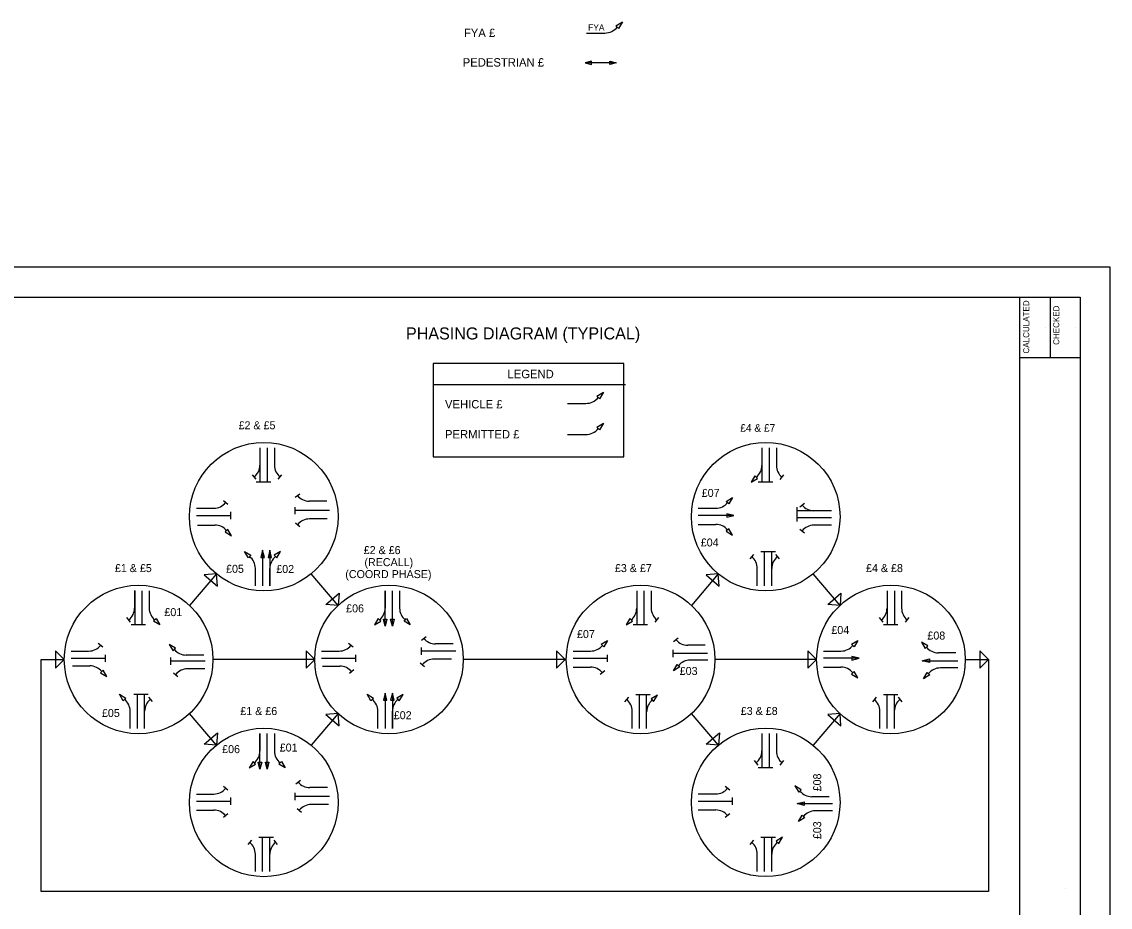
# Model space of a CAD drawing. Extents: x 22.8 to 118.4, y -49.9 to 44.8.
# Drawn here: x 57.13 to 75.22, y 29.96 to 44.69 of the extents above; entities that cross this region are included whole.
import ezdxf

# ---------------------------------------------------------------- set-up
doc = ezdxf.new("R2010")
doc.units = 0
for name, color, linetype in [('SH_Border', 7, 'Continuous'), ('SH_Cut_Line', 7, 'Continuous'), ('SH_Data', 7, 'Continuous'), ('SH_Text', 7, 'Continuous')]:
    doc.layers.add(name, color=color, linetype=linetype)

msp = doc.modelspace()

# ---------------------------------------------------------------- linework, layer by layer
at = {"layer": 'SH_Border'}
for p, q in [((73.72, 19.104), (73.72, 40.104)), ((74.22, 40.104), (74.22, 39.104)), ((73.72, 39.104), (74.72, 39.104))]:
    msp.add_line(p, q, dxfattribs=at)
msp.add_lwpolyline([(43.22, 40.104), (74.72, 40.104), (74.72, 19.104), (43.22, 19.104)], close=True, dxfattribs=at)
at = {"layer": 'SH_Cut_Line'}
msp.add_lwpolyline([(41.22, 18.604), (75.22, 18.604), (75.22, 40.604), (41.22, 40.604)], close=True, dxfattribs=at)
at = {"layer": 'SH_Data'}
for p, q in [((66.513, 44.498), (66.819, 44.498)), ((67.007, 44.001), (66.494, 44.001)), ((74.14, 39.607), (74.14, 39.607)), ((74.64, 39.607), (74.64, 39.607)), ((63.962, 38.652), (67.164, 38.652)), ((66.199, 38.338), (66.504, 38.338)), ((66.199, 37.822), (66.504, 37.822)), ((61.086, 37.6), (61.086, 37.029)), ((61.086, 37.6), (61.086, 37.31)), ((61.207, 37.6), (61.207, 37.029)), ((61.327, 37.6), (61.327, 37.31)), ((69.43, 37.599), (69.43, 37.028)), ((69.43, 37.599), (69.43, 37.308)), ((69.55, 37.599), (69.55, 37.028)), ((69.671, 37.599), (69.671, 37.308)), ((61.022, 37.076), (60.962, 37.151)), ((61.391, 37.076), (61.452, 37.151)), ((69.735, 37.074), (69.795, 37.15)), ((61.146, 37.029), (61.026, 37.029)), ((61.267, 37.029), (61.146, 37.029)), ((69.49, 37.028), (69.37, 37.028)), ((69.611, 37.028), (69.49, 37.028)), ((61.671, 36.777), (61.747, 36.837)), ((60.03, 36.595), (60.32, 36.595)), ((60.554, 36.659), (60.478, 36.72)), ((61.671, 36.495), (61.671, 36.615)), ((62.241, 36.555), (61.671, 36.555)), ((62.196, 36.713), (61.905, 36.713)), ((68.373, 36.594), (68.664, 36.594)), ((70.014, 36.494), (70.014, 36.614)), ((70.585, 36.554), (70.014, 36.554)), ((70.061, 36.617), (70.136, 36.678)), ((70.585, 36.554), (70.295, 36.554)), ((60.03, 36.475), (60.6, 36.475)), ((60.6, 36.414), (60.6, 36.535)), ((62.201, 36.417), (61.91, 36.417)), ((68.965, 36.473), (68.373, 36.473)), ((70.014, 36.373), (70.014, 36.494)), ((70.585, 36.433), (70.014, 36.433)), ((60.046, 36.316), (60.336, 36.316)), ((61.676, 36.353), (61.752, 36.292)), ((68.373, 36.327), (68.664, 36.327)), ((70.061, 36.249), (70.136, 36.188)), ((70.585, 36.313), (70.295, 36.313)), ((61.13, 35.896), (61.13, 35.304)), ((61.251, 35.896), (61.251, 35.304)), ((69.29, 35.828), (69.229, 35.752)), ((69.414, 35.874), (69.534, 35.874)), ((69.474, 35.303), (69.474, 35.874)), ((69.534, 35.874), (69.655, 35.874)), ((69.595, 35.303), (69.595, 35.874)), ((69.658, 35.828), (69.719, 35.752)), ((60.363, 35.503), (59.915, 34.979)), ((61.01, 35.304), (61.01, 35.595)), ((61.251, 35.304), (61.251, 35.595)), ((62.385, 34.979), (61.938, 35.504)), ((68.706, 35.502), (68.259, 34.979)), ((69.354, 35.303), (69.354, 35.593)), ((69.595, 35.303), (69.595, 35.593)), ((70.729, 34.979), (70.282, 35.503)), ((59.001, 35.225), (59.001, 34.934)), ((59.005, 35.224), (59.005, 34.654)), ((59.125, 35.224), (59.125, 34.654)), ((59.246, 35.224), (59.246, 34.934)), ((63.167, 34.633), (63.167, 35.224)), ((63.167, 35.224), (63.167, 34.934)), ((63.288, 34.633), (63.288, 35.224)), ((63.408, 35.224), (63.408, 34.934)), ((67.35, 35.224), (67.35, 34.654)), ((67.35, 35.224), (67.35, 34.934)), ((67.47, 35.224), (67.47, 34.654)), ((67.591, 35.224), (67.591, 34.934)), ((71.511, 35.224), (71.511, 34.654)), ((71.511, 35.224), (71.511, 34.934)), ((71.632, 35.224), (71.632, 34.654)), ((71.752, 35.224), (71.752, 34.934)), ((58.937, 34.7), (58.876, 34.776)), ((67.654, 34.7), (67.715, 34.776)), ((71.447, 34.7), (71.386, 34.776)), ((71.816, 34.7), (71.877, 34.776)), ((59.065, 34.654), (58.945, 34.654)), ((59.186, 34.654), (59.065, 34.654)), ((67.41, 34.654), (67.289, 34.654)), ((67.53, 34.654), (67.41, 34.654)), ((71.571, 34.654), (71.451, 34.654)), ((71.692, 34.654), (71.571, 34.654)), ((63.772, 34.401), (63.847, 34.462)), ((67.963, 34.378), (68.039, 34.439)), ((57.948, 34.22), (58.239, 34.22)), ((58.473, 34.283), (58.397, 34.344)), ((62.111, 34.22), (62.401, 34.22)), ((62.635, 34.283), (62.559, 34.344)), ((63.773, 34.159), (63.773, 34.28)), ((64.344, 34.22), (63.773, 34.22)), ((64.296, 34.338), (64.006, 34.338)), ((66.293, 34.219), (66.583, 34.219)), ((67.955, 34.119), (67.955, 34.24)), ((68.488, 34.315), (68.198, 34.315)), ((70.454, 34.219), (70.745, 34.219)), ((57.948, 34.099), (58.519, 34.099)), ((58.519, 34.039), (58.519, 34.159)), ((59.607, 33.991), (59.607, 34.112)), ((60.177, 34.052), (59.607, 34.052)), ((60.151, 34.153), (59.86, 34.153)), ((61.996, 34.079), (60.304, 34.079)), ((62.111, 34.099), (62.681, 34.099)), ((62.681, 34.039), (62.681, 34.159)), ((63.747, 34.022), (63.823, 33.961)), ((64.272, 34.086), (63.981, 34.086)), ((66.159, 34.079), (64.466, 34.079)), ((66.293, 34.099), (66.864, 34.099)), ((66.864, 34.039), (66.864, 34.159)), ((68.526, 34.179), (67.955, 34.179)), ((68.53, 34.07), (68.239, 34.07)), ((70.34, 34.079), (68.648, 34.079)), ((71.046, 34.099), (70.454, 34.099)), ((72.096, 34.059), (72.687, 34.059)), ((72.653, 34.191), (72.363, 34.191)), ((57.97, 33.973), (58.26, 33.973)), ((59.649, 33.86), (59.724, 33.799)), ((60.173, 33.923), (59.883, 33.923)), ((62.124, 33.969), (62.414, 33.969)), ((62.648, 33.905), (62.573, 33.845)), ((66.293, 33.953), (66.583, 33.953)), ((66.817, 33.889), (66.742, 33.828)), ((70.454, 33.953), (70.745, 33.953)), ((72.687, 33.938), (72.397, 33.938)), ((58.989, 33.5), (59.11, 33.5)), ((59.049, 32.929), (59.049, 33.5)), ((59.11, 33.5), (59.23, 33.5)), ((59.17, 32.929), (59.17, 33.5)), ((63.167, 33.521), (63.167, 32.929)), ((63.288, 33.521), (63.288, 32.929)), ((67.334, 33.499), (67.454, 33.499)), ((67.394, 32.929), (67.394, 33.499)), ((67.454, 33.499), (67.575, 33.499)), ((67.514, 32.929), (67.514, 33.499)), ((71.451, 33.499), (71.571, 33.499)), ((71.511, 32.929), (71.511, 33.499)), ((71.571, 33.499), (71.692, 33.499)), ((71.632, 32.929), (71.632, 33.499)), ((59.233, 33.453), (59.294, 33.378)), ((67.21, 33.453), (67.149, 33.377)), ((71.327, 33.453), (71.266, 33.377)), ((71.695, 33.453), (71.756, 33.377)), ((58.929, 32.929), (58.929, 33.219)), ((59.17, 32.929), (59.17, 33.219)), ((60.364, 32.654), (59.915, 33.179)), ((62.385, 33.179), (61.937, 32.654)), ((63.047, 32.929), (63.047, 33.219)), ((63.288, 32.929), (63.288, 33.219)), ((67.273, 32.929), (67.273, 33.219)), ((68.707, 32.655), (68.259, 33.179)), ((70.729, 33.179), (70.281, 32.654)), ((71.39, 32.929), (71.39, 33.219)), ((71.632, 32.929), (71.632, 33.219)), ((61.086, 32.847), (61.086, 32.557)), ((61.086, 32.255), (61.086, 32.847)), ((61.207, 32.255), (61.207, 32.847)), ((61.327, 32.847), (61.327, 32.557)), ((69.43, 32.848), (69.43, 32.278)), ((69.43, 32.848), (69.43, 32.558)), ((69.55, 32.848), (69.55, 32.278)), ((69.671, 32.848), (69.671, 32.558)), ((69.366, 32.324), (69.305, 32.4)), ((69.735, 32.324), (69.795, 32.4)), ((69.49, 32.278), (69.37, 32.278)), ((69.611, 32.278), (69.49, 32.278)), ((61.683, 32.012), (61.758, 32.072)), ((60.554, 31.906), (60.478, 31.966)), ((61.671, 31.742), (61.671, 31.862)), ((62.207, 31.948), (61.917, 31.948)), ((68.898, 31.907), (68.822, 31.968)), ((60.03, 31.842), (60.32, 31.842)), ((60.03, 31.721), (60.6, 31.721)), ((60.6, 31.661), (60.6, 31.782)), ((62.241, 31.802), (61.671, 31.802)), ((62.227, 31.666), (61.937, 31.666)), ((68.373, 31.843), (68.664, 31.843)), ((68.373, 31.723), (68.944, 31.723)), ((68.944, 31.663), (68.944, 31.783)), ((70.014, 31.683), (70.606, 31.683)), ((70.55, 31.798), (70.259, 31.798)), ((60.03, 31.575), (60.32, 31.575)), ((60.554, 31.512), (60.478, 31.451)), ((61.703, 31.603), (61.779, 31.542)), ((68.373, 31.577), (68.664, 31.577)), ((68.898, 31.513), (68.822, 31.452)), ((70.606, 31.562), (70.316, 31.562)), ((61.07, 31.122), (61.191, 31.122)), ((61.13, 30.551), (61.13, 31.122)), ((61.191, 31.122), (61.311, 31.122)), ((61.251, 30.551), (61.251, 31.122)), ((69.414, 31.123), (69.534, 31.123)), ((69.474, 30.553), (69.474, 31.123)), ((69.534, 31.123), (69.655, 31.123)), ((69.595, 30.553), (69.595, 31.123)), ((60.946, 31.076), (60.886, 31)), ((61.315, 31.076), (61.375, 31)), ((69.29, 31.077), (69.229, 31.001)), ((61.01, 30.551), (61.01, 30.842)), ((61.251, 30.551), (61.251, 30.842)), ((69.354, 30.553), (69.354, 30.843)), ((69.595, 30.553), (69.595, 30.843)), ((74.47, 30.27), (74.47, 30.27))]:
    msp.add_line(p, q, dxfattribs=at)
for points in [[(67.003, 44.619), (67.114, 44.686), (67.047, 44.575)], [(66.598, 44.028), (66.494, 44.001), (66.598, 43.975)], [(66.903, 44.028), (67.007, 44.001), (66.903, 43.975)], [(67.137, 39.002), (63.965, 39.002), (63.965, 37.451), (67.137, 37.451)], [(66.688, 38.46), (66.799, 38.526), (66.733, 38.415)], [(66.689, 37.943), (66.799, 38.009), (66.733, 37.898)], [(69.315, 37.133), (69.252, 37.028), (69.357, 37.091)], [(68.839, 36.709), (68.944, 36.772), (68.881, 36.667)], [(68.846, 36.444), (68.965, 36.473), (68.846, 36.503)], [(60.511, 36.201), (60.616, 36.138), (60.553, 36.243)], [(68.839, 36.212), (68.944, 36.149), (68.881, 36.254)], [(60.895, 35.77), (60.832, 35.875), (60.937, 35.812)], [(61.16, 35.777), (61.13, 35.896), (61.101, 35.777)], [(61.281, 35.777), (61.251, 35.896), (61.221, 35.777)], [(61.366, 35.77), (61.429, 35.875), (61.324, 35.812)], [(60.363, 35.503), (60.16, 35.487), (60.379, 35.3)], [(68.706, 35.502), (68.503, 35.487), (68.722, 35.299)], [(62.385, 34.979), (62.182, 34.995), (62.401, 35.182)], [(70.729, 34.979), (70.526, 34.995), (70.745, 35.182)], [(59.361, 34.759), (59.424, 34.654), (59.319, 34.717)], [(63.052, 34.759), (62.989, 34.654), (63.094, 34.717)], [(63.197, 34.751), (63.167, 34.633), (63.138, 34.751)], [(63.318, 34.751), (63.288, 34.633), (63.258, 34.751)], [(63.523, 34.759), (63.586, 34.654), (63.481, 34.717)], [(67.234, 34.759), (67.172, 34.654), (67.277, 34.717)], [(66.758, 34.335), (66.864, 34.397), (66.8, 34.292)], [(70.92, 34.335), (71.025, 34.397), (70.962, 34.292)], [(57.834, 34.079), (57.69, 34.223), (57.69, 33.935)], [(59.685, 34.268), (59.58, 34.331), (59.643, 34.226)], [(61.996, 34.079), (61.852, 34.223), (61.852, 33.935)], [(66.159, 34.079), (66.015, 34.223), (66.015, 33.935)], [(70.34, 34.079), (70.196, 34.223), (70.196, 33.935)], [(72.188, 34.306), (72.083, 34.369), (72.146, 34.264)], [(73.196, 34.079), (73.052, 34.223), (73.052, 33.935)], [(70.927, 34.069), (71.046, 34.099), (70.927, 34.129)], [(72.214, 34.029), (72.096, 34.059), (72.214, 34.089)], [(58.436, 33.858), (58.541, 33.795), (58.478, 33.9)], [(68.064, 33.955), (67.959, 33.892), (68.022, 33.997)], [(70.92, 33.838), (71.025, 33.775), (70.962, 33.88)], [(72.222, 33.823), (72.117, 33.76), (72.18, 33.865)], [(58.814, 33.394), (58.751, 33.5), (58.856, 33.436)], [(62.932, 33.394), (62.869, 33.5), (62.974, 33.436)], [(63.197, 33.402), (63.167, 33.521), (63.138, 33.402)], [(63.318, 33.402), (63.288, 33.521), (63.258, 33.402)], [(63.403, 33.394), (63.466, 33.499), (63.361, 33.436)], [(67.63, 33.383), (67.693, 33.488), (67.588, 33.425)], [(62.385, 33.179), (62.182, 33.163), (62.401, 32.976)], [(70.729, 33.179), (70.526, 33.163), (70.745, 32.976)], [(60.364, 32.654), (60.161, 32.67), (60.38, 32.857)], [(68.707, 32.655), (68.504, 32.671), (68.723, 32.858)], [(60.971, 32.381), (60.908, 32.276), (61.013, 32.339)], [(61.116, 32.374), (61.086, 32.255), (61.056, 32.374)], [(61.236, 32.374), (61.207, 32.255), (61.177, 32.374)], [(61.442, 32.381), (61.505, 32.276), (61.4, 32.339)], [(70.084, 31.913), (69.979, 31.976), (70.042, 31.871)], [(70.133, 31.653), (70.014, 31.683), (70.133, 31.713)], [(70.141, 31.447), (70.036, 31.384), (70.099, 31.489)], [(69.71, 31.018), (69.773, 31.123), (69.668, 31.06)]]:
    msp.add_lwpolyline(points, close=True, dxfattribs=at)
msp.add_lwpolyline([(72.81, 34.079), (73.196, 34.079), (73.196, 30.22), (57.834, 30.22), (57.448, 30.22), (57.448, 34.079), (57.834, 34.079)], dxfattribs=at)
for centre in [(61.15, 36.455), (69.494, 36.454), (59.069, 34.079), (63.231, 34.079), (67.414, 34.079), (71.575, 34.079), (61.15, 31.702), (69.494, 31.703)]:
    msp.add_circle(centre, 1.235, dxfattribs=at)
for centre, radius, start, end in [((66.819, 44.763), 0.265, 270, 321.2007), ((66.504, 38.603), 0.265, 270.0129, 321.2136), ((66.504, 38.087), 0.265, 270, 321.2007), ((60.834, 37.31), 0.252, 308.7864, 359.9871), ((61.579, 37.31), 0.252, 180.0129, 231.2136), ((69.178, 37.308), 0.252, 308.7993, 0), ((69.923, 37.308), 0.252, 180.0129, 231.2136), ((61.905, 36.965), 0.252, 218.7993, 270), ((60.32, 36.847), 0.252, 270, 321.2007), ((68.664, 36.846), 0.252, 270, 321.2007), ((70.295, 36.806), 0.252, 218.7993, 270), ((61.91, 36.165), 0.252, 90, 141.2007), ((60.336, 36.064), 0.252, 38.7864, 89.9871), ((68.664, 36.075), 0.252, 38.7993, 90), ((70.295, 36.061), 0.252, 90, 141.2007), ((60.758, 35.595), 0.252, 360, 51.2007), ((61.503, 35.595), 0.252, 128.7864, 179.9871), ((69.102, 35.593), 0.252, 360, 51.2007), ((69.847, 35.593), 0.252, 128.7993, 180), ((58.749, 34.934), 0.252, 308.7864, 359.9871), ((59.498, 34.934), 0.252, 180.0129, 231.2136), ((62.915, 34.934), 0.252, 308.7864, 359.9871), ((63.66, 34.934), 0.252, 180, 231.2007), ((67.098, 34.934), 0.252, 308.7993, 0), ((67.842, 34.934), 0.252, 180.0129, 231.2136), ((71.259, 34.934), 0.252, 308.7864, 359.9871), ((72.004, 34.934), 0.252, 180.0129, 231.2136), ((64.006, 34.59), 0.252, 218.7993, 270), ((68.198, 34.567), 0.252, 218.7993, 270), ((58.239, 34.471), 0.252, 270, 321.2007), ((59.86, 34.405), 0.252, 218.7864, 269.9871), ((62.401, 34.471), 0.252, 270, 321.2007), ((66.583, 34.471), 0.252, 270, 321.2007), ((70.745, 34.471), 0.252, 270, 321.2007), ((72.363, 34.443), 0.252, 218.7864, 269.9871), ((63.981, 33.834), 0.252, 90, 141.2007), ((68.239, 33.818), 0.252, 90, 141.2007), ((58.26, 33.721), 0.252, 38.7864, 89.9871), ((59.883, 33.672), 0.252, 90, 141.2007), ((62.414, 33.717), 0.252, 38.7993, 90), ((66.583, 33.701), 0.252, 38.7993, 90), ((70.745, 33.701), 0.252, 38.7993, 90), ((72.397, 33.687), 0.252, 90, 141.2007), ((58.677, 33.219), 0.252, 360, 51.2007), ((59.422, 33.219), 0.252, 128.7993, 180), ((62.795, 33.219), 0.252, 360, 51.2007), ((63.54, 33.219), 0.252, 128.7864, 179.9871), ((67.022, 33.219), 0.252, 360, 51.2007), ((67.767, 33.207), 0.252, 128.7993, 178.779), ((71.139, 33.219), 0.252, 360, 51.2007), ((71.883, 33.219), 0.252, 128.7993, 180), ((60.834, 32.557), 0.252, 308.7864, 359.9871), ((61.579, 32.557), 0.252, 180.0129, 231.2136), ((69.178, 32.558), 0.252, 308.7864, 359.9871), ((69.923, 32.558), 0.252, 180.0129, 231.2136), ((61.917, 32.2), 0.252, 218.7993, 270), ((60.32, 32.094), 0.252, 270, 321.2007), ((68.664, 32.095), 0.252, 270, 321.2007), ((70.259, 32.05), 0.252, 218.7864, 269.9871), ((61.937, 31.415), 0.252, 90, 141.2007), ((60.32, 31.323), 0.252, 38.7993, 90), ((68.664, 31.325), 0.252, 38.7993, 90), ((70.316, 31.31), 0.252, 90, 141.2007), ((60.758, 30.842), 0.252, 360, 51.2007), ((61.503, 30.842), 0.252, 128.7993, 180), ((69.102, 30.843), 0.252, 360, 51.2007), ((69.847, 30.843), 0.252, 128.7864, 179.9871)]:
    msp.add_arc(centre, radius, start, end, dxfattribs=at)

# ---------------------------------------------------------------- texts
for s, p in [('CALCULATED', (73.873, 39.168)), ('CHECKED', (74.373, 39.312))]:
    msp.add_text(s, height=0.1, rotation=90, dxfattribs=at).set_placement(p)
at = {"layer": 'SH_Text'}
for s, height, p in [('FYA £', 0.14, (64.477, 44.431)), ('FYA', 0.105, (66.541, 44.538)), ('PEDESTRIAN £', 0.14, (64.457, 43.94)), ('PHASING DIAGRAM (TYPICAL)', 0.2, (63.514, 39.402)), ('LEGEND', 0.14, (65.201, 38.757)), ('VEHICLE £', 0.14, (64.162, 38.255)), ('£2 & £5', 0.133, (60.731, 37.908)), ('PERMITTED £', 0.14, (64.162, 37.755)), ('£4 & £7', 0.1264, (69.07, 37.867)), ('£2 & £6', 0.133, (62.811, 35.832)), ('£1 & £5', 0.133, (58.675, 35.533)), ('(RECALL)', 0.133, (62.823, 35.632)), ('£3 & £7', 0.133, (66.987, 35.533)), ('£4 & £8', 0.133, (71.161, 35.533)), ('(COORD PHASE)', 0.13304, (62.505, 35.433)), ('£01', 0.133, (59.498, 34.801)), ('£07', 0.133, (66.357, 34.436)), ('£04', 0.133, (70.585, 34.503)), ('£03', 0.133, (68.064, 33.822)), ('£05', 0.133, (58.46, 33.123)), ('£1 & £6', 0.133, (60.76, 33.155)), ('£3 & £8', 0.133, (69.079, 33.157))]:
    msp.add_text(s, height=height, dxfattribs=at).set_placement(p)
for s, rotation, p in [('£07', 360, (68.43, 36.783)), ('£04', 360, (68.414, 35.959)), ('£05', 360, (60.523, 35.521)), ('£02', 360, (61.358, 35.518)), ('£06', 360, (62.519, 34.863)), ('£08', 360, (72.181, 34.411)), ('£02', 360, (63.311, 33.086)), ('£06', 360, (60.458, 32.522)), ('£01', 360, (61.415, 32.548)), ('£08', 90, (70.416, 31.886)), ('£03', 90, (70.416, 31.091))]:
    msp.add_text(s, height=0.133, rotation=rotation, dxfattribs=at).set_placement(p)

doc.saveas('drawing.dxf')
